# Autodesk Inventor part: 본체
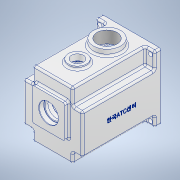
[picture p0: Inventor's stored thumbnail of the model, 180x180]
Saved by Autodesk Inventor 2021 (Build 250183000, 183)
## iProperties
Created: 2022-08
Part Number: 본체
Material: 알루미늄 6061
Document SubType Name: Modeling
Designer: Owner
Density: 2.7 g/cm^3
Appearance: 알루미늄 - 평지
Mass: 1404.2 g
Surface Area: 1170.75 cm^2
Volume: 520.075 cm^3
Author: Owner
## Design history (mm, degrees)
sketch "스케치1"
  geometry: L1 (-49, 55)-(49, 55); L2 (49, 55)-(49, -55); L3 (49, -55)-(-49, -55); L4 (-49, -55)-(-49, 55); L5 (-49, 55)-(49, -55); L6 (49, 55)-(-49, -55); 1 further point
  constraints: 12 end point, 2 midpoint, 2 parallel, 1 horizontal, 1 perpendicular
  dimensions: "d0" = 98 distance of L2.end L3.end; "d1" = 110 distance of L1.end L2.end
extrude "돌출1" new body sketch "스케치1" distance "d2" = 130; taper "d3" = 0 deg
sketch "스케치2"
  geometry: L1 (49, -55)-(49, 55) reference; L2 (49, 55)-(33, 55); L3 (33, 55)-(33, 28); L4 (33, 28)-(49, 28); L5 (49, 28)-(49, 55); L6 (49, 55)-(-49, 55) reference; L7 (-49, 55)-(-33, 55); L8 (-33, 55)-(-33, 28); L9 (-33, 28)-(-49, 28); L10 (-49, 28)-(-49, 55); L11 (-49, -55)-(49, -55) reference; L12 (-49, -55)-(-33, -55); L13 (-33, -55)-(-33, -38); L14 (-33, -38)-(-49, -38); L15 (-49, -38)-(-49, -55); L16 (49, -55)-(33, -55); L17 (33, -55)-(33, -38); L18 (33, -38)-(49, -38); L19 (49, -38)-(49, -55); 6 further points
  constraints: 32 end point, 8 parallel, 4 horizontal, 4 perpendicular
  dimensions: "d4" = 16 distance of L4.end L3.end; "d5" = 27 distance of L3.end L2.end; "d6" = 16 distance of L8.end L9.end; "d7" = 27 distance of L7.end L8.end; "d8" = 16 distance of L14.end L13.end; "d9" = 17 distance of L13.end L12.end; "d10" = 16 distance of L17.end L18.end; "d11" = 17 distance of L16.end L17.end
extrude "돌출2" cut sketch "스케치2" distance "d12" = 120; taper "d13" = 0 deg
sketch "스케치3"
  geometry: L1 (-27, 33)-(27, 33); L2 (27, 33)-(27, -21); L3 (27, -21)-(-27, -21); L4 (-27, -21)-(-27, 33); L5 (-27, 33)-(27, -21); L6 (27, 33)-(-27, -21); L7 (-33, -55)-(33, -55) reference; 3 further points
  constraints: 12 end point, 3 midpoint, 2 parallel, 1 horizontal, 1 perpendicular, 1 vertical alignment
  dimensions: "d149" = 54 distance of L2.end L3.end; "d150" = 54 distance of L1.end L2.end; "d151" = 61 distance from line of L7 point (0, 6)
extrude "돌출3" join sketch "스케치3" distance "d16" = 7; taper "d17" = 0 deg
sketch "스케치4"
  geometry: L1 (98, 0)-(0, 0) reference; C1 r 15 at (49, -89); C2 r 22.5 at (49, -40); 3 further points
  constraints: 2 centre point, 2 midpoint, 2 vertical alignment
  dimensions: "d18" = 30 diameter of C1; "d19" = 45 diameter of C2; "d20" = 40 distance of C2.centre point (49, 0); "d21" = 49 distance of C1.centre C2.centre
extrude "돌출4" join sketch "스케치4" distance "d22" = 5; taper "d23" = 0 deg
extrude "돌출5" join sketch "스케치4" distance "d24" = 10; taper "d25" = 0 deg
sketch "스케치5"
  geometry: L1 (49, -55)-(-49, -55) reference; L2 (-23, 30.143)-(-23, 45); L3 (-23, 45)-(23, 45); L4 (23, 45)-(23, 30.143); L5 (26, 31.729)-(26, 48); L6 (26, 48)-(-26, 48); L7 (-26, 48)-(-26, 31.729); A1 r 42 centre (0, -5) between (-23, 30.143) and (23, 30.143); A2 r 45 centre (0, -5) between (-26, 31.729) and (26, 31.729); 1 further point
  constraints: 12 end point, 4 perpendicular, 4 point on circle, 2 centre point, 1 vertical, 1 vertical alignment, 3 other
  dimensions: "d32" = 84 diameter of A1; "d33" = 50 distance from line of L1 A1.centre; "d34" = 50 distance from line of A1.centre L3; "d35" = 46 distance between parallel lines of L4 L2; "d36" = 23 distance from line of A1.centre L4; "d39" = 3 radial gap between concentric circles of A1 A2
extrude "돌출8" cut sketch "스케치5" distance "d40" = 9; taper "d41" = 0 deg
sketch "스케치6"
  geometry: L1 (23, 30.143)-(23, 45) reference; L2 (23, 45)-(-23, 45) reference; L3 (-23, 45)-(-23, 30.143) reference; L4 (49, -55)-(-49, -55) reference; L5 (-35.778, -1.006)-(-41.81, -1.006); L6 (-35.778, -8.994)-(-41.81, -8.994); L7 (41.81, -1.006)-(35.778, -1.006); L8 (41.81, -8.994)-(35.778, -8.994); L9 (-40, -5)-(40, -5); A1 r 42 centre (0, -5) between (-23, 30.143) and (23, 30.143) reference; A2 r 36 centre (0, -5) between (36, -5) and (-36, -5); A3 r 4 centre (36, -5) between (35.778, -1.006) and (35.778, -8.994); A4 r 4 centre (-36, -5) between (-35.778, -8.994) and (-35.778, -1.006); 1 further point
  constraints: 16 point on circle, 12 end point, 5 horizontal, 3 centre point, 2 point on line, 1 coincident, 1 midpoint
  dimensions: "d43" = 72 diameter of A2; "d46" = 4 radius of A3; "d47" = 4 radius of A4
extrude "돌출9" cut sketch "스케치6" distance "d48" = 114; taper "d49" = 0 deg
sketch "스케치7"
  geometry: L1 (-35.778, -1.006)-(-41.81, -1.006) reference; L2 (-41.81, -8.994)-(-35.778, -8.994) reference; L3 (35.778, -8.994)-(41.81, -8.994) reference; L4 (41.81, -1.006)-(35.778, -1.006) reference; L5 (23, 45)-(23, 30.143) reference; L6 (-23, 45)-(23, 45) reference; L7 (-23, 30.143)-(-23, 45) reference; A1 r 42 centre (0, -5) between (-23, 30.143) and (-41.81, -1.006) reference; A2 r 4 centre (-36, -5) between (-35.778, -8.994) and (-35.778, -1.006) reference; A3 r 42 centre (0, -5) between (-41.81, -8.994) and (41.81, -8.994) reference; A4 r 4 centre (36, -5) between (35.778, -1.006) and (35.778, -8.994) reference; A5 r 42 centre (0, -5) between (41.81, -1.006) and (23, 30.143) reference; A6 r 21 centre (0, 6) between (8.978, -12.984) and (-8.978, -12.984); A7 r 15 centre (0, -25) between (-8.978, -12.984) and (8.978, -12.984); 1 further point
  constraints: 4 point on circle, 2 centre point, 2 vertical alignment
  dimensions: "d50" = 30 diameter of A7; "d51" = 42 diameter of A6; "d52" = 20 distance of A7.centre A1.centre; "d53" = 11 distance of A1.centre A6.centre
extrude "돌출10" cut sketch "스케치7" distance "d54" = 7; taper "d55" = 0 deg
sketch "스케치8"
  geometry: A1 r 21 centre (0, 6) between (8.978, -12.984) and (-8.978, -12.984) reference; 2 further points
  constraints: 1 coincident
hole "구멍1" sketch "스케치8" at (0, 6) diameter "d56" = 28; stored, may be unused: countersink angle "d60" = 90 deg, drill point angle "d62" = 118 deg; dims "d57" = 6, "d58" = 35, "d59" = 10, "d61" = 8
sketch "스케치10"
  geometry: A1 r 15 centre (0, -25) between (-8.978, -12.984) and (8.978, -12.984) reference; 2 further points
  constraints: 1 coincident
hole "구멍3" sketch "스케치10" at (0, -25) diameter "d70" = 19; stored, may be unused: countersink angle "d74" = 90 deg, drill point angle "d76" = 0 deg; dims "d71" = 6, "d72" = 22, "d73" = 7, "d75" = 10
sketch "스케치11"
  geometry: C1 r 22.5 at (0, 0) reference; 2 further points
  constraints: 1 coincident
hole "구멍4" sketch "스케치11" at (0, 0) diameter "d77" = 33.376; stored, may be unused: countersink angle "d81" = 90 deg, drill point angle "d83" = 0 deg; dims "d78" = 70, "d79" = 22, "d80" = 7, "d82" = 77.3
sketch "스케치12"
  geometry: C1 r 15 at (23, 80) reference; 2 further points
  constraints: 1 coincident
hole "구멍5" sketch "스케치12" at (23, 80) diameter "d84" = 20; stored, may be unused: countersink angle "d88" = 90 deg, drill point angle "d90" = 0 deg; dims "d85" = 70, "d86" = 30, "d87" = 5, "d89" = 77.3
sketch "스케치13"
  geometry: L1 (-41.81, -8.994)-(-35.778, -8.994) reference; L2 (-35.778, -1.006)-(-41.81, -1.006) reference; L3 (35.778, -8.994)-(41.81, -8.994) reference; L4 (41.81, -1.006)-(35.778, -1.006) reference; A1 r 4 centre (-36, -5) between (-35.778, -8.994) and (-35.778, -1.006) reference; A2 r 42 centre (0, -5) between (-41.81, -1.006) and (-41.81, -8.994) reference; A3 r 42 centre (0, -5) between (41.81, -8.994) and (41.81, -1.006) reference; A4 r 4 centre (36, -5) between (35.778, -1.006) and (35.778, -8.994) reference; 1 further point
extrude "돌출11" cut sketch "스케치13" distance "d91" = 9; taper "d92" = 0 deg
sketch "스케치14"
  geometry: A1 r 45 centre (0, -5) between (-26, 31.729) and (26, 31.729) reference; 3 further points
  constraints: 2 horizontal alignment
  dimensions: "d93" = 36 distance of A1.centre point (36, -5); "d94" = 36 distance of A1.centre point (-36, -5)
hole "구멍6" sketch "스케치14" at (-36, -5), (36, -5) diameter "d95" = 3.242; stored, may be unused: countersink angle "d99" = 90 deg, drill point angle "d101" = 118 deg; dims "d96" = 7, "d97" = 30, "d98" = 5, "d100" = 9
sketch "스케치15"
  geometry: L1 (-49, -55)-(-49, 55) reference; L2 (-49, 55)-(49, 55) reference; C1 r 3.5 at (-42, 48); 1 further point
  constraints: 1 centre point
  dimensions: "d102" = 7 diameter of C1; "d103" = 7 distance from line of L1 C1.centre; "d104" = 7 distance from line of C1.centre L2
extrude "돌출12" cut sketch "스케치15" distance "d105" = 10; taper "d106" = 0 deg
fillet "모깎기1" dims "d107" = 3
fillet "모깎기2" dims "d108" = 0.3
fillet "모깎기3" dims "d112" = 0.3
fillet "모깎기4" dims "d116" = 6
chamfer "모따기3" distance "d117" = 1; stored, may be unused: second distance "d118" = 2, angle "d119" = 30 deg
chamfer "모따기4" distance "d120" = 1; stored, may be unused: second distance "d121" = 2, angle "d122" = 30 deg
fillet "모깎기5" dims "d126" = 3
fillet "모깎기6" dims "d127" = 3
fillet "모깎기7" dims "d128" = 3
fillet "모깎기8" dims "d129" = 3
fillet "모깎기9" dims "d130" = 3
fillet "모깎기10" dims "d131" = 6
fillet "모깎기11" dims "d135" = 3
fillet "모깎기12" dims "d136" = 3
fillet "모깎기13" dims "d137" = 3
fillet "모깎기14" dims "d138" = 3
fillet "모깎기15" dims "d139" = 3
fillet "모깎기16" dims "d140" = 3
fillet "모깎기17" dims "d141" = 3
fillet "모깎기18" dims "d142" = 3
fillet "모깎기19" dims "d143" = 3
fillet "모깎기20" dims "d144" = 3
fillet "모깎기21" dims "d145" = 3
fillet "모깎기22" dims "d146" = 3
fillet "모깎기23" dims "d147" = 3
fillet "모깎기24" dims "d148" = 3
fillet "모깎기25" dims "d152" = 3
fillet "모깎기26" dims "d153" = 3
sketch "스케치16"
  geometry: C1 r 14 at (0, 6) reference; 2 further points
  constraints: 1 coincident
hole "구멍7" sketch "스케치16" at (0, 6) diameter "d154" = 32; stored, may be unused: countersink angle "d158" = 90 deg, drill point angle "d160" = 0 deg; dims "d155" = 7, "d156" = 30, "d157" = 5, "d159" = 8.3
chamfer "모따기7" distance "d161" = 0.8; stored, may be unused: second distance "d162" = 2, angle "d163" = 30 deg
fillet "모깎기27" dims "d164" = 0.3
fillet "모깎기28" dims "d165" = 3
sketch "스케치17"
  geometry: L1 (0, 0)-(0, 60) reference; L2 (117, 63)-(3, 63) reference; 2 further points
  constraints: 1 other
  dimensions: "d166" = 65 distance from line of L1 point (65, 30); "d167" = 33 distance from line of L2 point (65, 30)
feature "엠보싱1" sketch "스케치17" dims "d6" = 16, "d7" = 27, "d168" = 0.5, "d169" = 0
fillet "모깎기29" dims "d173" = 3
chamfer "모따기9" distance "d174" = 1; stored, may be unused: second distance "d175" = 2, angle "d176" = 30 deg
node "솔리드1"
mirror "미러1"
mirror "미러2"
node "투영된 루프1"
node "투영된 루프2"
node "투영된 루프3"
node "투영된 루프4"
feature "A9D066F2-1C7D-4E18-AEED-F7BC21143FA4" dims "d70" = 19, "d71" = 6, "d72" = 22, "d73" = 7, "d74" = 90 deg, "d75" = 10, "d76" = 0
